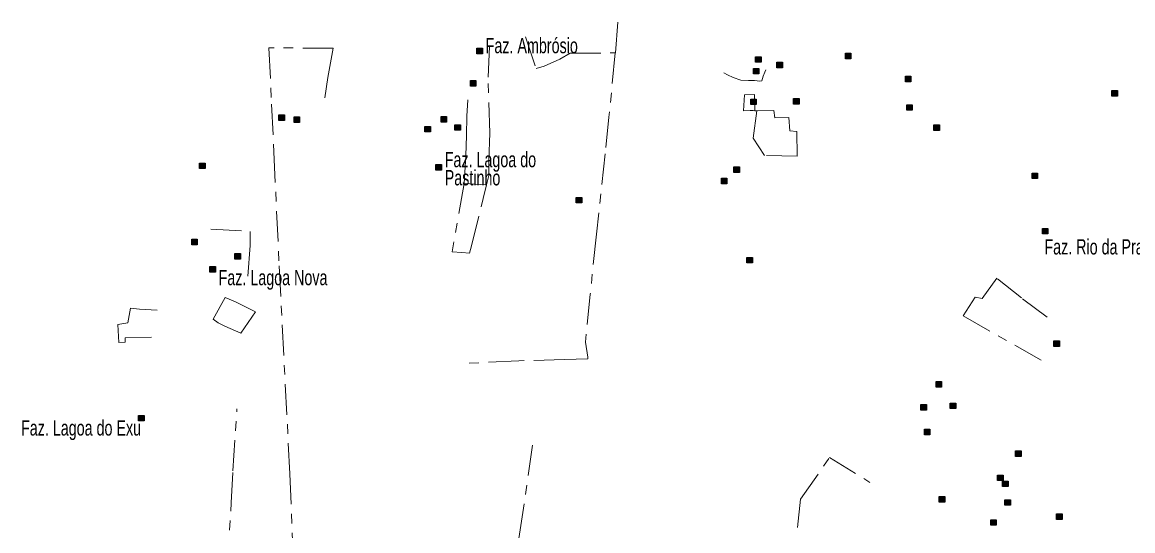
# Model space of a CAD drawing. Extents: x 445.4 to 500, y 8728.7 to 8784.
# Drawn here: x 470.25 to 481.88, y 8778.68 to 8784 of the extents above; entities that cross this region are included whole.
import ezdxf

# ---------------------------------------------------------------- set-up
doc = ezdxf.new("R2010")
doc.units = 0
doc.header["$LTSCALE"] = 0.064
doc.linetypes.add('DOT_DASHED', pattern=[7.7, 5, -1.2, 0.3, -1.2])
doc.layers.add('2', color=7, linetype='Continuous', lineweight=25)
doc.layers.add('22', color=7, linetype='DOT_DASHED', lineweight=13)
doc.layers.add('61', color=7, linetype='Continuous')

msp = doc.modelspace()

# ---------------------------------------------------------------- hatches: boundary and pattern name
at = {"layer": '2'}
for points in [[(475.0149, 8783.7266), (475.0729, 8783.7266), (475.0729, 8783.6686), (475.0149, 8783.6686)], [(477.9335, 8783.6378), (477.9915, 8783.6378), (477.9915, 8783.5798), (477.9335, 8783.5798)], [(478.8747, 8783.674), (478.9327, 8783.674), (478.9327, 8783.616), (478.8747, 8783.616)], [(477.9109, 8783.5156), (477.9689, 8783.5156), (477.9689, 8783.4576), (477.9109, 8783.4576)], [(478.1567, 8783.5789), (478.2147, 8783.5789), (478.2147, 8783.5209), (478.1567, 8783.5209)], [(474.947, 8783.387), (475.005, 8783.387), (475.005, 8783.329), (474.947, 8783.329)], [(479.5037, 8783.4341), (479.5617, 8783.4341), (479.5617, 8783.3761), (479.5037, 8783.3761)], [(481.6667, 8783.2828), (481.7247, 8783.2828), (481.7247, 8783.2248), (481.6667, 8783.2248)], [(477.8838, 8783.1941), (477.9418, 8783.1941), (477.9418, 8783.1361), (477.8838, 8783.1361)], [(478.3317, 8783.1986), (478.3897, 8783.1986), (478.3897, 8783.1406), (478.3317, 8783.1406)], [(479.5173, 8783.1353), (479.5753, 8783.1353), (479.5753, 8783.0773), (479.5173, 8783.0773)], [(472.9424, 8783.0294), (473.0004, 8783.0294), (473.0004, 8782.9714), (472.9424, 8782.9714)], [(473.1008, 8783.0067), (473.1588, 8783.0067), (473.1588, 8782.9487), (473.1008, 8782.9487)], [(474.6393, 8783.0113), (474.6973, 8783.0113), (474.6973, 8782.9533), (474.6393, 8782.9533)], [(474.7841, 8782.9252), (474.8421, 8782.9252), (474.8421, 8782.8672), (474.7841, 8782.8672)], [(479.8021, 8782.9233), (479.8601, 8782.9233), (479.8601, 8782.8653), (479.8021, 8782.8653)], [(474.4697, 8782.9086), (474.5277, 8782.9086), (474.5277, 8782.8506), (474.4697, 8782.8506)], [(472.1098, 8782.5239), (472.1678, 8782.5239), (472.1678, 8782.4659), (472.1098, 8782.4659)], [(474.585, 8782.5087), (474.643, 8782.5087), (474.643, 8782.4507), (474.585, 8782.4507)], [(477.7064, 8782.4833), (477.7644, 8782.4833), (477.7644, 8782.4253), (477.7064, 8782.4253)], [(477.5761, 8782.3656), (477.6341, 8782.3656), (477.6341, 8782.3076), (477.5761, 8782.3076)], [(480.8295, 8782.4199), (480.8875, 8782.4199), (480.8875, 8782.3619), (480.8295, 8782.3619)], [(476.0555, 8782.1649), (476.1135, 8782.1649), (476.1135, 8782.1069), (476.0555, 8782.1069)], [(480.9381, 8781.8403), (480.9961, 8781.8403), (480.9961, 8781.7823), (480.9381, 8781.7823)], [(472.0283, 8781.7271), (472.0863, 8781.7271), (472.0863, 8781.6691), (472.0283, 8781.6691)], [(472.4808, 8781.5777), (472.5388, 8781.5777), (472.5388, 8781.5197), (472.4808, 8781.5197)], [(477.843, 8781.5371), (477.901, 8781.5371), (477.901, 8781.4791), (477.843, 8781.4791)], [(472.2184, 8781.4418), (472.2764, 8781.4418), (472.2764, 8781.3838), (472.2184, 8781.3838)], [(481.0592, 8780.6633), (481.1172, 8780.6633), (481.1172, 8780.6053), (481.0592, 8780.6053)], [(479.825, 8780.2377), (479.883, 8780.2377), (479.883, 8780.1797), (479.825, 8780.1797)], [(479.9723, 8780.0134), (480.0303, 8780.0134), (480.0303, 8779.9554), (479.9723, 8779.9554)], [(479.6661, 8779.9964), (479.7241, 8779.9964), (479.7241, 8779.9384), (479.6661, 8779.9384)], [(471.4717, 8779.8844), (471.5297, 8779.8844), (471.5297, 8779.8264), (471.4717, 8779.8264)], [(479.7028, 8779.7397), (479.7608, 8779.7397), (479.7608, 8779.6817), (479.7028, 8779.6817)], [(480.6564, 8779.5125), (480.7144, 8779.5125), (480.7144, 8779.4545), (480.6564, 8779.4545)], [(480.4675, 8779.2598), (480.5255, 8779.2598), (480.5255, 8779.2018), (480.4675, 8779.2018)], [(480.5218, 8779.1964), (480.5798, 8779.1964), (480.5798, 8779.1384), (480.5218, 8779.1384)], [(479.8567, 8779.0334), (479.9147, 8779.0334), (479.9147, 8778.9754), (479.8567, 8778.9754)], [(480.5445, 8779.0017), (480.6025, 8779.0017), (480.6025, 8778.9437), (480.5445, 8778.9437)], [(481.0857, 8778.8531), (481.1437, 8778.8531), (481.1437, 8778.7951), (481.0857, 8778.7951)], [(480.3973, 8778.7926), (480.4553, 8778.7926), (480.4553, 8778.7346), (480.3973, 8778.7346)]]:
    msp.add_hatch(color=256, dxfattribs=at).paths.add_polyline_path(points)

# ---------------------------------------------------------------- linework, layer by layer
for points in [[(475.0149, 8783.7266), (475.0729, 8783.7266), (475.0729, 8783.6686), (475.0149, 8783.6686)], [(477.9335, 8783.6378), (477.9915, 8783.6378), (477.9915, 8783.5798), (477.9335, 8783.5798)], [(478.8747, 8783.674), (478.9327, 8783.674), (478.9327, 8783.616), (478.8747, 8783.616)], [(477.9109, 8783.5156), (477.9689, 8783.5156), (477.9689, 8783.4576), (477.9109, 8783.4576)], [(478.1567, 8783.5789), (478.2147, 8783.5789), (478.2147, 8783.5209), (478.1567, 8783.5209)], [(474.947, 8783.387), (475.005, 8783.387), (475.005, 8783.329), (474.947, 8783.329)], [(479.5037, 8783.4341), (479.5617, 8783.4341), (479.5617, 8783.3761), (479.5037, 8783.3761)], [(481.6667, 8783.2828), (481.7247, 8783.2828), (481.7247, 8783.2248), (481.6667, 8783.2248)], [(477.8838, 8783.1941), (477.9418, 8783.1941), (477.9418, 8783.1361), (477.8838, 8783.1361)], [(478.3317, 8783.1986), (478.3897, 8783.1986), (478.3897, 8783.1406), (478.3317, 8783.1406)], [(479.5173, 8783.1353), (479.5753, 8783.1353), (479.5753, 8783.0773), (479.5173, 8783.0773)], [(472.9424, 8783.0294), (473.0004, 8783.0294), (473.0004, 8782.9714), (472.9424, 8782.9714)], [(473.1008, 8783.0067), (473.1588, 8783.0067), (473.1588, 8782.9487), (473.1008, 8782.9487)], [(474.6393, 8783.0113), (474.6973, 8783.0113), (474.6973, 8782.9533), (474.6393, 8782.9533)], [(474.7841, 8782.9252), (474.8421, 8782.9252), (474.8421, 8782.8672), (474.7841, 8782.8672)], [(479.8021, 8782.9233), (479.8601, 8782.9233), (479.8601, 8782.8653), (479.8021, 8782.8653)], [(474.4697, 8782.9086), (474.5277, 8782.9086), (474.5277, 8782.8506), (474.4697, 8782.8506)], [(472.1098, 8782.5239), (472.1678, 8782.5239), (472.1678, 8782.4659), (472.1098, 8782.4659)], [(474.585, 8782.5087), (474.643, 8782.5087), (474.643, 8782.4507), (474.585, 8782.4507)], [(477.7064, 8782.4833), (477.7644, 8782.4833), (477.7644, 8782.4253), (477.7064, 8782.4253)], [(477.5761, 8782.3656), (477.6341, 8782.3656), (477.6341, 8782.3076), (477.5761, 8782.3076)], [(480.8295, 8782.4199), (480.8875, 8782.4199), (480.8875, 8782.3619), (480.8295, 8782.3619)], [(476.0555, 8782.1649), (476.1135, 8782.1649), (476.1135, 8782.1069), (476.0555, 8782.1069)], [(480.9381, 8781.8403), (480.9961, 8781.8403), (480.9961, 8781.7823), (480.9381, 8781.7823)], [(472.0283, 8781.7271), (472.0863, 8781.7271), (472.0863, 8781.6691), (472.0283, 8781.6691)], [(472.4808, 8781.5777), (472.5388, 8781.5777), (472.5388, 8781.5197), (472.4808, 8781.5197)], [(477.843, 8781.5371), (477.901, 8781.5371), (477.901, 8781.4791), (477.843, 8781.4791)], [(472.2184, 8781.4418), (472.2764, 8781.4418), (472.2764, 8781.3838), (472.2184, 8781.3838)], [(481.0592, 8780.6633), (481.1172, 8780.6633), (481.1172, 8780.6053), (481.0592, 8780.6053)], [(479.825, 8780.2377), (479.883, 8780.2377), (479.883, 8780.1797), (479.825, 8780.1797)], [(479.9723, 8780.0134), (480.0303, 8780.0134), (480.0303, 8779.9554), (479.9723, 8779.9554)], [(479.6661, 8779.9964), (479.7241, 8779.9964), (479.7241, 8779.9384), (479.6661, 8779.9384)], [(471.4717, 8779.8844), (471.5297, 8779.8844), (471.5297, 8779.8264), (471.4717, 8779.8264)], [(479.7028, 8779.7397), (479.7608, 8779.7397), (479.7608, 8779.6817), (479.7028, 8779.6817)], [(480.6564, 8779.5125), (480.7144, 8779.5125), (480.7144, 8779.4545), (480.6564, 8779.4545)], [(480.4675, 8779.2598), (480.5255, 8779.2598), (480.5255, 8779.2018), (480.4675, 8779.2018)], [(480.5218, 8779.1964), (480.5798, 8779.1964), (480.5798, 8779.1384), (480.5218, 8779.1384)], [(479.8567, 8779.0334), (479.9147, 8779.0334), (479.9147, 8778.9754), (479.8567, 8778.9754)], [(480.5445, 8779.0017), (480.6025, 8779.0017), (480.6025, 8778.9437), (480.5445, 8778.9437)], [(481.0857, 8778.8531), (481.1437, 8778.8531), (481.1437, 8778.7951), (481.0857, 8778.7951)], [(480.3973, 8778.7926), (480.4553, 8778.7926), (480.4553, 8778.7346), (480.3973, 8778.7346)]]:
    msp.add_lwpolyline(points, close=True, dxfattribs=at)
at = {"layer": '22'}
for p, q in [((476.4928, 8783.9982), (476.4651, 8783.6768)), ((477.9267, 8783.0719), (477.9268, 8783.0719)), ((475.1172, 8782.2978), (474.883, 8782.3105))]:
    msp.add_line(p, q, dxfattribs=at)
for points in [[(475.1172, 8782.2978), (475.1414, 8782.3926), (475.1414, 8782.5499), (475.1501, 8782.8381), (475.1324, 8783.4249), (475.1513, 8783.8271)], [(475.5258, 8783.8461), (475.6359, 8783.5139), (475.7191, 8783.5371), (475.8823, 8783.6103), (475.9922, 8783.6735), (476.4651, 8783.6768)], [(473.4215, 8783.2082), (473.4555, 8783.4182), (473.5112, 8783.7269), (472.8373, 8783.7299), (472.8651, 8783.1403), (472.8894, 8782.6418), (472.9436, 8781.4491), (473.0567, 8779.2734), (473.0994, 8778.2292), (473.1347, 8777.6598), (473.1632, 8776.9766), (473.2059, 8776.4832), (473.2624, 8775.7596)], [(476.4651, 8783.6768), (476.3985, 8783.005), (476.357, 8782.6198), (476.2669, 8781.7812), (476.2025, 8781.1522), (476.1509, 8780.6502), (476.1765, 8780.4937), (476.1765, 8780.4766), (475.9317, 8780.468), (475.4548, 8780.4551), (474.8552, 8780.4257)], [(477.6017, 8783.4671), (477.6383, 8783.4464), (477.6977, 8783.42), (477.7801, 8783.3925), (477.8602, 8783.389), (477.9219, 8783.3868), (477.9803, 8783.3822), (477.9997, 8783.3845), (478.0134, 8783.4326), (478.0317, 8783.4762), (478.0397, 8783.4992)], [(474.883, 8782.3105), (474.8976, 8782.6008), (474.9075, 8782.8121), (474.9108, 8783.0147), (474.9191, 8783.1859)], [(477.9262, 8783.0719), (477.9226, 8783.2414), (477.8163, 8783.2377), (477.8087, 8783.0707)], [(477.8087, 8783.0707), (477.8756, 8783.0728), (477.9091, 8783.0728), (477.9262, 8783.0719)], [(477.9262, 8783.0719), (477.9425, 8783.0716), (477.9483, 8783.0716)], [(474.883, 8782.3105), (474.7561, 8781.5942), (474.8567, 8781.5898), (474.9368, 8781.5818), (474.9573, 8781.6597), (475.0801, 8782.1524), (475.1172, 8782.2978)], [(472.2299, 8781.8325), (472.6408, 8781.8098), (472.6408, 8781.6604), (472.6153, 8781.3418)], [(480.9878, 8780.9126), (480.7178, 8781.1142), (480.4611, 8781.3182), (480.3065, 8781.1059), (480.2348, 8781.1225), (480.1078, 8780.924), (480.9425, 8780.4528)], [(471.6653, 8780.9861), (471.4798, 8780.9972), (471.3864, 8781.0045), (471.3603, 8780.8508), (471.2531, 8780.8365), (471.2661, 8780.6452), (471.3306, 8780.6491), (471.3322, 8780.6958), (471.6074, 8780.701)], [(472.398, 8778.2635), (472.4425, 8778.968), (472.4596, 8779.3039), (472.5025, 8779.9532)], [(475.5987, 8779.571), (475.5049, 8778.9128), (475.3863, 8778.1926), (475.3626, 8778.0078), (475.196, 8776.9328), (475.1296, 8776.4874), (475.1055, 8776.3224)], [(478.372, 8778.709), (478.405, 8779.0065), (478.7097, 8779.444), (479.1323, 8779.1823)]]:
    msp.add_lwpolyline(points, dxfattribs=at)
for points in [[(477.9483, 8783.0716), (478.1264, 8783.0733), (478.1363, 8782.9994), (478.2819, 8783.0018), (478.2918, 8782.8613), (478.3658, 8782.8564), (478.3683, 8782.5951), (478.0276, 8782.6025), (477.9072, 8782.7863)], [(472.3069, 8780.8541), (472.2531, 8780.8921), (472.3785, 8781.1185), (472.4858, 8781.0715), (472.695, 8780.9661), (472.5439, 8780.7441), (472.3751, 8780.8165)]]:
    msp.add_lwpolyline(points, close=True, dxfattribs=at)

# ---------------------------------------------------------------- texts
at = {"layer": '61', "width": 0.7}
for s, p in [('Faz. Ambrósio', (475.1069, 8783.6739)), ('Faz. Lagoa do', (474.678, 8782.4811)), ('Pastinho', (474.678, 8782.2911)), ('Faz. Rio da Prata', (480.9591, 8781.5679)), ('Faz. Lagoa Nova', (472.3095, 8781.2463)), ('Faz. Lagoa do Exu', (470.2406, 8779.673))]:
    msp.add_text(s, height=0.16, dxfattribs=at).set_placement(p)

doc.saveas('drawing.dxf')
